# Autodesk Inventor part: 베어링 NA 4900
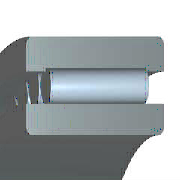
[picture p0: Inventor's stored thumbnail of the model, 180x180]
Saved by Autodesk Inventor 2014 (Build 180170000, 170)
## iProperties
Created: 2009-02
Part Number: 베어링 NA 4900
Material: Steel, Mild
Description: 니들 롤러 베어링 - 경계 치수 및 공차
Document SubType Name: Modeling
Standard: KS B 2029
Designer: SeoGD™
Standards Organization: KS
Language: ko-KR
Size Designation: NA 4900 - 10 x 22 x 13
Categories: <MemberInstance><Categories><Category DisplayName="샤프트 부품" InternalName="7f7aeb1f-a693-4053-b835-cee3144e0d98" Mnemonic="SHFT"><Category DisplayName="베어링" Inter
Density: 7.86 g/cm^3
Appearance: Metal-Steel
Mass: 23.8213 g
Surface Area: 38.613 cm^2
Volume: 3.0307 cm^3
IsCustomPart: 0
Author: SeoGD™
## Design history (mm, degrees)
sketch "스케치"
  geometry: L1 (1.857, 9)-(11.143, 9); L2 (11.143, 9)-(11.143, 7); L3 (13, 7)-(0, 7); L4 (1.857, 7)-(1.857, 9); L5 (1.857, 8)-(11.143, 8); L6 (6.5, 8)-(6.5, 7); L7 (0, 5)-(13, 5); L8 (0, 11)-(13, 11); L9 (13, 5)-(13, 7); L10 (13, 8.8)-(13, 11); L11 (1.857, 8.8)-(0, 8.8); L12 (11.143, 8.8)-(13, 8.8); L13 (-6, 0)-(36, 0) reference; L14 (0, -1.9)-(0, 14.9) reference
  constraints: 24 end point, 8 point on line, 3 midpoint, 3 parallel, 3 perpendicular, 2 symmetric about line, 1 horizontal, 1 other
  dimensions: "d6" = 10 diameter of L7 L13 (= WD); "d7" = 14 diameter of L3 L13 (= KID1); "d8" = 22 diameter of L8 L13 (= BD); "d9" = 16 diameter of L6.start L13 (= 0.5 x WD + 0.5 x BD); "d10" = 17.6 diameter of L12 L13 (= 0.9 x BD + 0.9 x WD - 0.8 x KID1); "d11" = 18 diameter of L1 L13 (= BD + WD - KID1); "d12" = 1.85714 distance between parallel lines of L14 L4 (= 0.142857 x KB); "d13" = 13 distance between parallel lines of L14 L9 (= KB); "d14" = 11.14286 distance between parallel lines of L14 L2 (= 0.857143 x KB)
revolve "본체" stored, may be unused: angle "d17" = 90 deg
revolve "롤러" stored, may be unused: angle "d18" = 90 deg
pattern_circular "IDS_ARRAYROLLER[SIMPL:T]" dims angle "d2" = 360 deg
body "Solid1"
fillet "모깎기1" dims "d0" = 0.3 (= KRS)
other parameters: "WD" = 10 [user parameter; used in 6 equation terms], "BD" = 22 [user parameter; used in 6 equation terms], "KB" = 13 [user parameter; used in 3 equation terms], "KID1" = 14 [user parameter; used in 4 equation terms], "KRS" = 0.3 [user parameter; used in 1 equation term], "d3" = 0, "d4" = 0, "d5" = 0, "d15" = 0, "d16" = 0, "BC0" = 9150000 [user parameter], "WR" = 5 (= 0.5 x WD) [user parameter], "BBA" = 0 [user parameter], "BC" = 8150000 [user parameter], "BR" = 11 (= 0.5 x BD) [user parameter]
